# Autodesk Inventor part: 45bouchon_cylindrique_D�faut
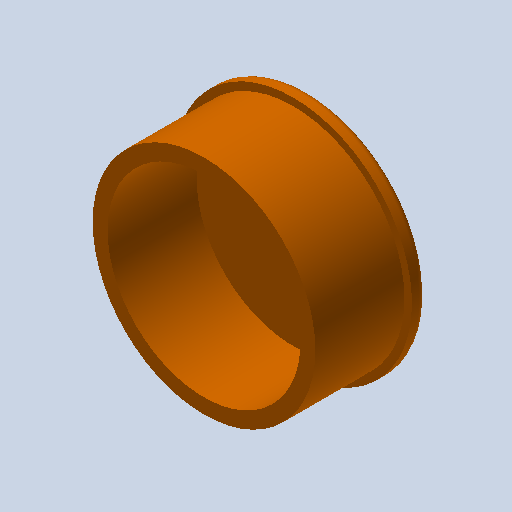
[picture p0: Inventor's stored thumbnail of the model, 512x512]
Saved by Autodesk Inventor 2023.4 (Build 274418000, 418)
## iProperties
Created: 2011-01
Part Number: 45bouchon_cylindrique_D�faut
Document SubType Name: Modeling
Designer: eric
Density: 1 g/cm^3
Mass: 3.69837 g
Surface Area: 38.7711 cm^2
Volume: 3.69837 cm^3
Material: Générique
Appearance: 255,128,0_1
Author: eric
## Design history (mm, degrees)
feature "Base1"
node "Corps solides"
node "Corps surfaciques"
node "Solide1"
